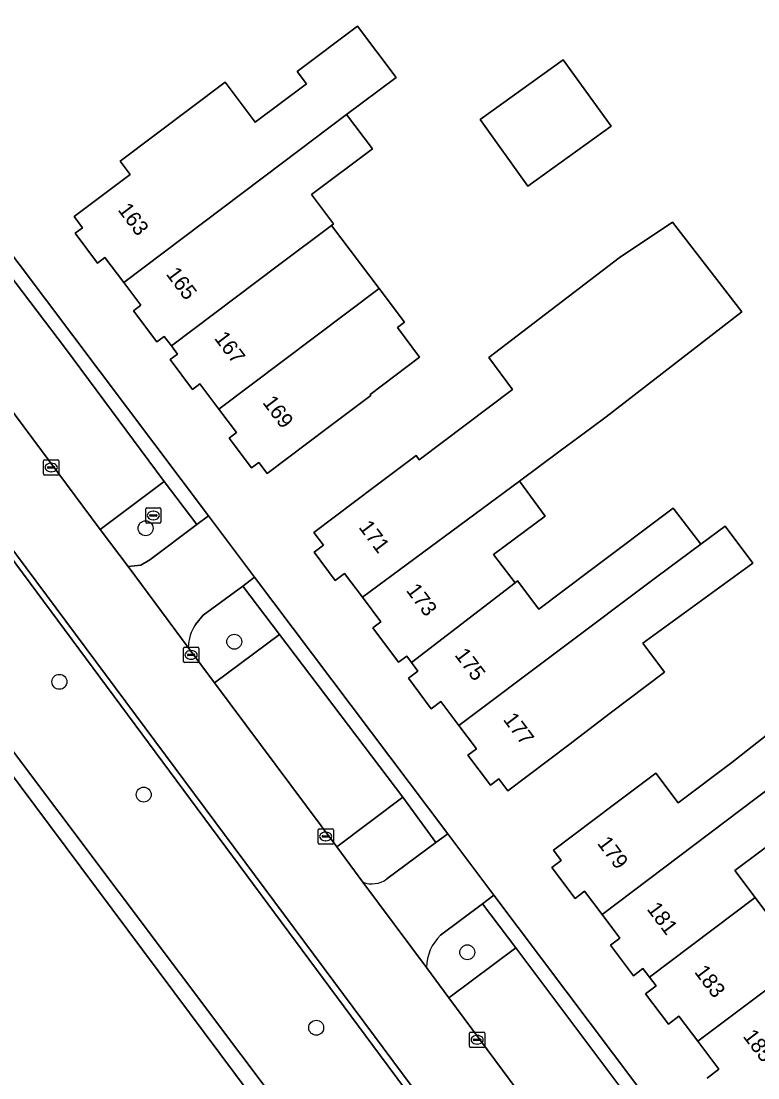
# Model space of a CAD drawing. Extents: x 164494 to 166241, y 382475 to 384495.
# Drawn here: x 165019 to 165067.3, y 383171.9 to 383241.1 of the extents above; entities that cross this region are included whole.
import ezdxf

# ---------------------------------------------------------------- set-up
doc = ezdxf.new("R2010")
doc.units = 0
for name, color, linetype in [('IMGEO_Berm_halfverhard', 7, 'Continuous'), ('IMGEO_Boom', 7, 'Continuous'), ('IMGEO_Erf', 7, 'Continuous'), ('IMGEO_Grasland_agrarisch', 7, 'Continuous'), ('IMGEO_Groenvoorziening', 7, 'Continuous'), ('IMGEO_Haag', 7, 'Continuous'), ('IMGEO_Hek', 7, 'Continuous'), ('IMGEO_Kolk', 7, 'Continuous'), ('IMGEO_Pand', 7, 'Continuous'), ('IMGEO_Pand_nummerreeks', 7, 'Continuous'), ('IMGEO_Parkeervlak_open', 7, 'Continuous'), ('IMGEO_Rijbaan_lokaal_gesloten', 7, 'Continuous'), ('IMGEO_Rioolput', 7, 'Continuous'), ('IMGEO_Voetpad_open', 7, 'Continuous')]:
    doc.layers.add(name, color=color, linetype=linetype)

msp = doc.modelspace()

# ---------------------------------------------------------------- linework, layer by layer
at = {"layer": 'IMGEO_Berm_halfverhard'}
msp.add_lwpolyline([(164958.624, 383286.837), (164958.165, 383286.487), (164958.551, 383285.995), (164958.685, 383286.071), (164960.201, 383284.12), (164981.497, 383255.445), (165004.699, 383224.274), (165010.162, 383216.934), (165012.663, 383213.574), (165041.519, 383174.67), (165059.934, 383149.875), (165074.189, 383130.821), (165074.54, 383131.069), (165010.834, 383216.638), (165007.308, 383221.332), (165004.939, 383224.601), (164967.779, 383274.687)], close=True, dxfattribs=at)
at = {"layer": 'IMGEO_Boom'}
for centre in [(165027.124, 383207.892), (165032.942, 383200.456), (165021.479, 383197.829), (165027.003, 383190.44), (165048.216, 383180.108), (165038.31, 383175.163)]:
    msp.add_circle(centre, 0.489, dxfattribs=at)
at = {"layer": 'IMGEO_Erf'}
for points in [[(165015.239, 383229.95), (165031.244, 383208.7), (165034.273, 383204.678), (165046.93, 383187.872), (165049.957, 383183.853), (165062.528, 383167.161), (165066.135, 383162.372), (165069.455, 383163.492), (165113.129, 383179.617), (165117.672, 383182.875), (165120.913, 383186.942), (165121.542, 383188.741), (165121.938, 383191.314), (165121.806, 383193.491), (165121.345, 383196.328), (165115.938, 383208.997), (165099.323, 383243.435)], [(165063.937, 383171.865), (165064.71, 383172.45), (165063.327, 383174.281), (165062.085, 383175.926), (165061.398, 383175.407), (165059.901, 383177.389), (165060.588, 383177.908), (165060.161, 383178.473), (165059.728, 383179.046), (165059.102, 383178.573), (165057.593, 383180.571), (165058.22, 383181.044), (165057.061, 383182.578), (165055.907, 383184.106), (165055.28, 383183.633), (165053.752, 383185.657), (165054.378, 383186.13), (165053.869, 383186.804), (165057.867, 383189.808), (165060.586, 383191.852), (165062.046, 383189.909), (165065.549, 383192.541), (165073.025, 383198.419)], [(165069.021, 383187.921), (165065.758, 383185.469), (165067.089, 383183.698), (165068.56, 383181.741)]]:
    msp.add_lwpolyline(points, dxfattribs=at)
for points in [[(165040.306, 383234.996), (165041.999, 383232.745), (165037.992, 383229.754), (165039.442, 383227.824), (165039.32, 383227.733), (165042.434, 383223.59), (165044.092, 383221.384), (165043.63, 383221.036), (165045.093, 383219.09), (165041.852, 383216.653), (165041.899, 383216.591), (165039.091, 383214.48), (165035.095, 383211.477), (165034.545, 383212.208), (165034.065, 383211.847), (165032.597, 383213.802), (165033.077, 383214.162), (165031.936, 383215.681), (165030.685, 383217.345), (165030.205, 383216.984), (165028.74, 383218.935), (165029.22, 383219.295), (165028.815, 383219.834), (165028.345, 383220.458), (165027.866, 383220.098), (165026.332, 383222.139), (165026.812, 383222.499), (165025.693, 383223.987), (165024.46, 383225.628), (165023.981, 383225.268), (165022.515, 383227.218), (165022.994, 383227.578), (165022.444, 383228.31), (165026.116, 383231.071), (165025.463, 383231.939), (165032.34, 383237.107), (165034.309, 383234.487), (165037.665, 383237.013), (165037.064, 383237.812), (165041.018, 383240.789), (165043.542, 383237.432)], [(165052.184, 383230.308), (165049.053, 383234.664), (165054.509, 383238.585), (165057.64, 383234.23)], [(165058.178, 383225.614), (165061.671, 383227.945), (165066.223, 383222.066), (165057.315, 383215.185), (165056.376, 383214.489), (165054.302, 383212.954), (165051.631, 383210.976), (165053.321, 383208.692), (165049.929, 383206.18), (165051.355, 383204.324), (165051.511, 383204.444), (165052.899, 383202.597), (165056.183, 383205.065), (165061.704, 383209.216), (165063.52, 383206.844), (165065.122, 383208.035), (165066.933, 383205.599), (165059.726, 383200.352), (165061.149, 383198.459), (165057.586, 383195.781), (165054.871, 383193.698), (165050.874, 383190.694), (165050.291, 383191.47), (165049.732, 383191.049), (165048.25, 383193.021), (165048.81, 383193.441), (165047.656, 383194.976), (165046.486, 383196.532), (165045.857, 383196.059), (165044.352, 383198.061), (165044.982, 383198.534), (165044.554, 383199.103), (165044.243, 383199.517), (165043.706, 383199.114), (165042.014, 383201.366), (165042.551, 383201.769), (165041.352, 383203.364), (165040.174, 383204.932), (165039.56, 383204.471), (165038.171, 383206.319), (165038.784, 383206.78), (165038.158, 383207.613), (165042.156, 383210.617), (165044.86, 383212.649), (165045.063, 383212.378), (165051.186, 383216.981), (165049.617, 383219.07)]]:
    msp.add_lwpolyline(points, close=True, dxfattribs=at)
at = {"layer": 'IMGEO_Grasland_agrarisch'}
msp.add_lwpolyline([(164980.914, 383148.382), (164984.464, 383145.593), (164986.079, 383147.55), (164989.095, 383145.351), (164987.398, 383143.288), (164988.7, 383142.265), (164990.041, 383144.274), (164992.369, 383142.607), (164990.882, 383140.55), (164991.336, 383140.194), (164999.033, 383132.273), (165005.383, 383122.26), (165055.217, 383142.364), (165001.686, 383214.058), (164971.559, 383197.218), (164924.278, 383170.366), (164950.628, 383163.159), (164961.434, 383158.935), (164968.553, 383155.492), (164979.763, 383149.202), (164979.818, 383149.302), (164980.837, 383150.538), (164981.966, 383149.612), (164980.98, 383148.501)], close=True, dxfattribs=at)
at = {"layer": 'IMGEO_Groenvoorziening'}
for points in [[(165131.174, 383055.545), (165127.167, 383060.515), (165121.14, 383068.038), (165114.948, 383075.929), (165110.383, 383081.771), (165084.231, 383116.963), (165084.718, 383117.313), (165084.235, 383117.963), (165074.593, 383130.998), (165074.54, 383131.069), (165074.189, 383130.821), (165059.934, 383149.875), (165041.519, 383174.67), (165012.663, 383213.574), (165010.162, 383216.934)], [(165004.905, 383120.773), (165057.111, 383141.834), (165001.652, 383215.597), (164998.338, 383213.696), (164970.712, 383197.845), (164920.991, 383170.02), (164950.25, 383162.018), (164960.954, 383157.835), (164967.997, 383154.428), (164979.176, 383148.155), (164979.763, 383149.202), (164968.553, 383155.492), (164961.434, 383158.935), (164950.628, 383163.159), (164924.278, 383170.366), (164971.559, 383197.218), (165001.686, 383214.058), (165055.217, 383142.364), (165005.383, 383122.26)], [(165001.652, 383215.597), (165057.111, 383141.834), (165064.424, 383130.625), (165069.489, 383132.355)], [(165029.916, 383200.087), (165031.646, 383197.767), (165035.91, 383200.939), (165033.499, 383204.106), (165030.905, 383202.188), (165030.4, 383201.58)], [(165042.937, 383184.911), (165046.148, 383187.292), (165043.994, 383190.272), (165039.657, 383187.007), (165041.362, 383184.698)], [(165045.531, 383179.12), (165047.015, 383177.125), (165051.395, 383180.401), (165049.207, 383183.29), (165046.456, 383181.223)]]:
    msp.add_lwpolyline(points, dxfattribs=at)
msp.add_lwpolyline([(165026.806, 383205.467), (165027.415, 383205.813), (165030.492, 383208.133), (165028.355, 383210.944), (165024.153, 383207.813), (165025.987, 383205.384)], close=True, dxfattribs=at)
for centre, radius, start, end in [((165032.787, 383199.981), 2.873, 146.18542, 177.89132), ((165041.952, 383186.268), 1.677, 249.41318, 305.99051), ((165048.637, 383179.009), 3.108, 134.56655, 177.94907)]:
    msp.add_arc(centre, radius, start, end, dxfattribs=at)
at = {"layer": 'IMGEO_Haag'}
msp.add_lwpolyline([(165004.905, 383120.773), (165057.111, 383141.834), (165001.652, 383215.597), (164998.338, 383213.696), (164970.712, 383197.845), (164920.991, 383170.02), (164950.25, 383162.018), (164960.954, 383157.835), (164967.997, 383154.428), (164979.176, 383148.155), (164979.763, 383149.202), (164968.553, 383155.492), (164961.434, 383158.935), (164950.628, 383163.159), (164924.278, 383170.366), (164971.559, 383197.218), (165001.686, 383214.058), (165055.217, 383142.364), (165005.383, 383122.26)], dxfattribs=at)
at = {"layer": 'IMGEO_Hek'}
msp.add_lwpolyline([(165005.383, 383122.26), (165055.217, 383142.364), (165001.686, 383214.058), (164971.559, 383197.218), (164924.278, 383170.366), (164950.628, 383163.159), (164961.434, 383158.935), (164968.553, 383155.492), (164979.763, 383149.202)], dxfattribs=at)
at = {"layer": 'IMGEO_Kolk'}
for p, q in [((165020.44, 383211.447), (165020.44, 383212.299)), ((165020.515, 383212.373), (165021.367, 383212.373)), ((165020.699, 383211.867), (165020.699, 383211.879)), ((165021.137, 383211.83), (165020.739, 383211.83)), ((165020.742, 383211.916), (165021.14, 383211.916)), ((165020.928, 383212.153), (165020.953, 383212.153)), ((165021.183, 383211.879), (165021.183, 383211.867)), ((165021.441, 383212.299), (165021.441, 383211.447)), ((165021.367, 383211.373), (165020.515, 383211.373)), ((165020.951, 383211.593), (165020.926, 383211.593)), ((165029.61, 383199.166), (165029.61, 383200.018)), ((165029.685, 383200.092), (165030.537, 383200.092)), ((165030.611, 383200.018), (165030.611, 383199.166)), ((165029.869, 383199.586), (165029.869, 383199.598)), ((165030.307, 383199.549), (165029.909, 383199.549)), ((165029.912, 383199.635), (165030.31, 383199.635)), ((165030.121, 383199.312), (165030.096, 383199.312)), ((165030.098, 383199.872), (165030.123, 383199.872)), ((165030.353, 383199.598), (165030.353, 383199.586)), ((165030.537, 383199.092), (165029.685, 383199.092)), ((165038.433, 383187.271), (165038.433, 383188.123)), ((165038.508, 383188.197), (165039.36, 383188.197)), ((165038.692, 383187.691), (165038.692, 383187.703)), ((165039.13, 383187.654), (165038.732, 383187.654)), ((165038.735, 383187.74), (165039.133, 383187.74)), ((165038.921, 383187.977), (165038.946, 383187.977)), ((165039.176, 383187.703), (165039.176, 383187.691)), ((165039.434, 383188.123), (165039.434, 383187.271)), ((165039.36, 383187.197), (165038.508, 383187.197)), ((165038.944, 383187.417), (165038.919, 383187.417)), ((165048.36, 383173.953), (165048.36, 383174.805)), ((165048.435, 383174.879), (165049.287, 383174.879)), ((165048.619, 383174.373), (165048.619, 383174.385)), ((165048.662, 383174.422), (165049.06, 383174.422)), ((165048.848, 383174.659), (165048.873, 383174.659)), ((165049.103, 383174.385), (165049.103, 383174.373)), ((165049.361, 383174.805), (165049.361, 383173.953)), ((165049.287, 383173.879), (165048.435, 383173.879)), ((165049.057, 383174.336), (165048.659, 383174.336)), ((165048.871, 383174.099), (165048.846, 383174.099))]:
    msp.add_line(p, q, dxfattribs=at)
for points in [[(165020.44, 383211.447), (165020.44, 383212.299)], [(165020.515, 383212.373), (165021.367, 383212.373)], [(165021.441, 383212.299), (165021.441, 383211.447)], [(165021.367, 383211.373), (165020.515, 383211.373)], [(165029.61, 383199.166), (165029.61, 383200.018)], [(165029.685, 383200.092), (165030.537, 383200.092)], [(165030.611, 383200.018), (165030.611, 383199.166)], [(165030.537, 383199.092), (165029.685, 383199.092)], [(165038.433, 383187.271), (165038.433, 383188.123)], [(165038.508, 383188.197), (165039.36, 383188.197)], [(165039.434, 383188.123), (165039.434, 383187.271)], [(165039.36, 383187.197), (165038.508, 383187.197)], [(165048.36, 383173.953), (165048.36, 383174.805)], [(165048.435, 383174.879), (165049.287, 383174.879)], [(165049.361, 383174.805), (165049.361, 383173.953)], [(165049.287, 383173.879), (165048.435, 383173.879)]]:
    msp.add_lwpolyline(points, dxfattribs=at)
for centre, radius, start, end in [((165020.517, 383212.297), 0.0765, 91.55205, 178.44795), ((165020.517, 383212.297), 0.0765, 91.55205, 178.44795), ((165020.739, 383211.876), 0.0403, 85.87752, 175.75265), ((165020.736, 383211.866), 0.0366, 178.93798, 274.71019), ((165021.14, 383211.873), 0.043, 264.86636, 352.45326), ((165021.144, 383211.878), 0.0386, 1.73085, 96.63898), ((165021.365, 383212.297), 0.0765, 1.55205, 88.44795), ((165021.365, 383212.297), 0.0765, 1.55205, 88.44795), ((165020.517, 383211.449), 0.0765, 181.55205, 268.44795), ((165020.517, 383211.449), 0.0765, 181.55205, 268.44795), ((165021.365, 383211.449), 0.0765, 271.55205, 358.44795), ((165021.365, 383211.449), 0.0765, 271.55205, 358.44795), ((165029.687, 383200.016), 0.0765, 91.55205, 178.44795), ((165029.687, 383200.016), 0.0765, 91.55205, 178.44795), ((165030.535, 383200.016), 0.0765, 1.55205, 88.44795), ((165030.535, 383200.016), 0.0765, 1.55205, 88.44795), ((165029.909, 383199.595), 0.0403, 85.87752, 175.75265), ((165029.906, 383199.585), 0.0366, 178.93798, 274.71019), ((165030.31, 383199.592), 0.043, 264.86636, 352.45326), ((165030.314, 383199.597), 0.0386, 1.73085, 96.63898), ((165029.687, 383199.168), 0.0765, 181.55205, 268.44795), ((165029.687, 383199.168), 0.0765, 181.55205, 268.44795), ((165030.535, 383199.168), 0.0765, 271.55205, 358.44795), ((165030.535, 383199.168), 0.0765, 271.55205, 358.44795), ((165038.51, 383188.121), 0.0765, 91.55205, 178.44795), ((165038.51, 383188.121), 0.0765, 91.55205, 178.44795), ((165038.732, 383187.7), 0.0403, 85.87752, 175.75265), ((165038.729, 383187.69), 0.0366, 178.93798, 274.71019), ((165039.133, 383187.697), 0.043, 264.86636, 352.45326), ((165039.137, 383187.702), 0.0386, 1.73085, 96.63898), ((165039.358, 383188.121), 0.0765, 1.55205, 88.44795), ((165039.358, 383188.121), 0.0765, 1.55205, 88.44795), ((165038.51, 383187.273), 0.0765, 181.55205, 268.44795), ((165038.51, 383187.273), 0.0765, 181.55205, 268.44795), ((165039.358, 383187.273), 0.0765, 271.55205, 358.44795), ((165039.358, 383187.273), 0.0765, 271.55205, 358.44795), ((165048.437, 383174.803), 0.0765, 91.55205, 178.44795), ((165048.437, 383174.803), 0.0765, 91.55205, 178.44795), ((165048.659, 383174.382), 0.0403, 85.87752, 175.75265), ((165048.656, 383174.372), 0.0366, 178.93798, 274.71019), ((165049.06, 383174.379), 0.043, 264.86636, 352.45326), ((165049.064, 383174.384), 0.0386, 1.73085, 96.63898), ((165049.285, 383174.803), 0.0765, 1.55205, 88.44795), ((165049.285, 383174.803), 0.0765, 1.55205, 88.44795), ((165048.437, 383173.955), 0.0765, 181.55205, 268.44795), ((165048.437, 383173.955), 0.0765, 181.55205, 268.44795), ((165049.285, 383173.955), 0.0765, 271.55205, 358.44795), ((165049.285, 383173.955), 0.0765, 271.55205, 358.44795)]:
    msp.add_arc(centre, radius, start, end, dxfattribs=at)
for centre, major_axis, ratio, start_param, end_param in [((165020.927, 383211.873), (-0.387, 0.002), 0.722429, 4.712389, 7.853982), ((165020.952, 383211.873), (-0.39, 0.002), 0.717154, 1.570796, 4.712389), ((165030.097, 383199.592), (-0.387, 0.002), 0.722429, 4.712389, 7.853982), ((165030.122, 383199.592), (-0.39, 0.002), 0.717154, 1.570796, 4.712389), ((165038.92, 383187.697), (-0.387, 0.002), 0.722429, 4.712389, 7.853982), ((165038.945, 383187.697), (-0.39, 0.002), 0.717154, 1.570796, 4.712389), ((165048.847, 383174.379), (-0.387, 0.002), 0.722429, 4.712389, 7.853982), ((165048.872, 383174.379), (-0.39, 0.002), 0.717154, 1.570796, 4.712389)]:
    msp.add_ellipse(centre, major_axis=major_axis, ratio=ratio, start_param=start_param, end_param=end_param, dxfattribs=at)
at = {"layer": 'IMGEO_Pand'}
for points in [[(165040.306, 383234.996), (165043.542, 383237.432), (165041.018, 383240.789), (165037.064, 383237.812), (165037.665, 383237.013), (165034.309, 383234.487), (165032.34, 383237.107), (165025.463, 383231.939), (165026.116, 383231.071), (165022.444, 383228.31), (165022.994, 383227.578), (165022.515, 383227.218), (165023.981, 383225.268), (165024.46, 383225.628), (165025.693, 383223.987), (165036.095, 383231.826)], [(165054.509, 383238.585), (165049.053, 383234.664), (165052.184, 383230.308), (165057.64, 383234.23)], [(165039.32, 383227.733), (165039.442, 383227.824), (165037.992, 383229.754), (165041.999, 383232.745), (165040.306, 383234.996), (165036.095, 383231.826), (165025.693, 383223.987), (165026.812, 383222.499), (165026.332, 383222.139), (165027.866, 383220.098), (165028.345, 383220.458), (165028.815, 383219.834), (165035.845, 383225.12)], [(165042.434, 383223.59), (165039.32, 383227.733), (165035.845, 383225.12), (165028.815, 383219.834), (165029.22, 383219.295), (165028.74, 383218.935), (165030.205, 383216.984), (165030.685, 383217.345), (165031.936, 383215.681)], [(165051.631, 383210.976), (165054.302, 383212.954), (165056.376, 383214.489), (165057.315, 383215.185), (165066.223, 383222.066), (165061.671, 383227.945), (165058.178, 383225.614), (165049.617, 383219.07), (165051.186, 383216.981), (165045.063, 383212.378), (165044.86, 383212.649), (165042.156, 383210.617), (165038.158, 383207.613), (165038.784, 383206.78), (165038.171, 383206.319), (165039.56, 383204.471), (165040.174, 383204.932), (165041.352, 383203.364)], [(165042.434, 383223.59), (165031.936, 383215.681), (165033.077, 383214.162), (165032.597, 383213.802), (165034.065, 383211.847), (165034.545, 383212.208), (165035.095, 383211.477), (165039.091, 383214.48), (165041.899, 383216.591), (165041.852, 383216.653), (165045.093, 383219.09), (165043.63, 383221.036), (165044.092, 383221.384)], [(165069.932, 383192.285), (165072.484, 383194.21), (165075.031, 383196.131), (165087.792, 383205.569), (165083.664, 383211.659), (165076.095, 383206.151), (165078.583, 383202.656), (165073.025, 383198.419), (165065.549, 383192.541), (165062.046, 383189.909), (165060.586, 383191.852), (165057.867, 383189.808), (165053.869, 383186.804), (165054.378, 383186.13), (165053.752, 383185.657), (165055.28, 383183.633), (165055.907, 383184.106), (165057.061, 383182.578), (165067.16, 383190.195)], [(165051.631, 383210.976), (165041.352, 383203.364), (165042.551, 383201.769), (165042.014, 383201.366), (165043.706, 383199.114), (165044.243, 383199.517), (165044.554, 383199.103), (165051.355, 383204.324), (165049.929, 383206.18), (165053.321, 383208.692)], [(165060.641, 383204.704), (165063.52, 383206.844), (165061.704, 383209.216), (165056.183, 383205.065), (165052.899, 383202.597), (165051.511, 383204.444), (165051.355, 383204.324), (165044.554, 383199.103), (165044.982, 383198.534), (165044.352, 383198.061), (165045.857, 383196.059), (165046.486, 383196.532), (165047.656, 383194.976)], [(165061.149, 383198.459), (165059.726, 383200.352), (165066.933, 383205.599), (165065.122, 383208.035), (165063.52, 383206.844), (165060.641, 383204.704), (165047.656, 383194.976), (165048.81, 383193.441), (165048.25, 383193.021), (165049.732, 383191.049), (165050.291, 383191.47), (165050.874, 383190.694), (165054.871, 383193.698), (165057.586, 383195.781)], [(165071.696, 383189.901), (165069.932, 383192.285), (165067.16, 383190.195), (165057.061, 383182.578), (165058.22, 383181.044), (165057.593, 383180.571), (165059.102, 383178.573), (165059.728, 383179.046), (165060.161, 383178.473), (165067.089, 383183.698), (165065.758, 383185.469), (165069.021, 383187.921)], [(165078.372, 383185.544), (165076.657, 383187.826), (165071.802, 383184.178), (165068.56, 383181.741), (165067.089, 383183.698), (165060.161, 383178.473), (165060.588, 383177.908), (165059.901, 383177.389), (165061.398, 383175.407), (165062.085, 383175.926), (165063.327, 383174.281)]]:
    msp.add_lwpolyline(points, close=True, dxfattribs=at)
msp.add_lwpolyline([(165076.723, 383171.76), (165076.536, 383172.007), (165076.129, 383171.7), (165073.526, 383175.147), (165077.499, 383178.149), (165077.807, 383177.742), (165078.054, 383177.929), (165077.747, 383178.336), (165081.545, 383181.204), (165081.853, 383180.797), (165082.1, 383180.984), (165084.045, 383178.409), (165097.149, 383188.306), (165092.15, 383194.924), (165079.047, 383185.026), (165078.553, 383185.68), (165078.372, 383185.544), (165063.327, 383174.281), (165064.71, 383172.45), (165063.937, 383171.865)], dxfattribs=at)
at = {"layer": 'IMGEO_Parkeervlak_open'}
for points in [[(165010.316, 383226.399), (165024.153, 383207.813), (165028.355, 383210.944), (165021.887, 383219.675), (165014.428, 383229.447)], [(165039.657, 383187.007), (165043.994, 383190.272), (165035.91, 383200.939), (165031.646, 383197.767)], [(165051.395, 383180.401), (165047.015, 383177.125), (165054.99, 383166.374), (165059.454, 383169.659)]]:
    msp.add_lwpolyline(points, close=True, dxfattribs=at)
at = {"layer": 'IMGEO_Rijbaan_lokaal_gesloten'}
for points in [[(165074.593, 383130.998), (165078.641, 383134.022), (165066.076, 383150.934), (165060.749, 383158.104), (165061.002, 383158.295), (165057.36, 383163.251), (165054.99, 383166.374), (165047.015, 383177.125), (165045.531, 383179.12), (165041.362, 383184.698), (165039.657, 383187.007), (165031.646, 383197.767), (165029.916, 383200.087), (165025.987, 383205.384), (165024.153, 383207.813), (165010.316, 383226.399)], [(165010.834, 383216.638), (165074.54, 383131.069)]]:
    msp.add_lwpolyline(points, dxfattribs=at)
at = {"layer": 'IMGEO_Rioolput'}
for p, q in [((165027.134, 383208.301), (165027.134, 383209.153)), ((165027.209, 383209.227), (165028.061, 383209.227)), ((165027.622, 383209.007), (165027.647, 383209.007)), ((165028.135, 383209.153), (165028.135, 383208.301)), ((165027.393, 383208.721), (165027.393, 383208.733)), ((165027.831, 383208.684), (165027.433, 383208.684)), ((165027.436, 383208.77), (165027.834, 383208.77)), ((165027.645, 383208.447), (165027.62, 383208.447)), ((165027.877, 383208.733), (165027.877, 383208.721)), ((165028.061, 383208.227), (165027.209, 383208.227))]:
    msp.add_line(p, q, dxfattribs=at)
for points in [[(165027.134, 383208.301), (165027.134, 383209.153)], [(165027.209, 383209.227), (165028.061, 383209.227)], [(165028.135, 383209.153), (165028.135, 383208.301)], [(165028.061, 383208.227), (165027.209, 383208.227)]]:
    msp.add_lwpolyline(points, dxfattribs=at)
for centre, radius, start, end in [((165027.211, 383209.151), 0.0765, 91.55205, 178.44795), ((165027.211, 383209.151), 0.0765, 91.55205, 178.44795), ((165028.059, 383209.151), 0.0765, 1.55205, 88.44795), ((165028.059, 383209.151), 0.0765, 1.55205, 88.44795), ((165027.211, 383208.303), 0.0765, 181.55205, 268.44795), ((165027.211, 383208.303), 0.0765, 181.55205, 268.44795), ((165027.433, 383208.73), 0.0403, 85.87752, 175.75265), ((165027.43, 383208.72), 0.0366, 178.93798, 274.71019), ((165027.834, 383208.727), 0.043, 264.86636, 352.45326), ((165027.838, 383208.732), 0.0386, 1.73085, 96.63898), ((165028.059, 383208.303), 0.0765, 271.55205, 358.44795), ((165028.059, 383208.303), 0.0765, 271.55205, 358.44795)]:
    msp.add_arc(centre, radius, start, end, dxfattribs=at)
for centre, major_axis, ratio, start_param, end_param in [((165027.621, 383208.727), (-0.387, 0.002), 0.722429, 4.712389, 7.853982), ((165027.646, 383208.727), (-0.39, 0.002), 0.717154, 1.570796, 4.712389)]:
    msp.add_ellipse(centre, major_axis=major_axis, ratio=ratio, start_param=start_param, end_param=end_param, dxfattribs=at)
at = {"layer": 'IMGEO_Voetpad_open'}
for points in [[(165012.159, 383232.511), (165014.428, 383229.447), (165021.887, 383219.675), (165028.355, 383210.944), (165030.492, 383208.133), (165031.244, 383208.7), (165015.239, 383229.95), (165012.902, 383233.067)], [(165035.91, 383200.939), (165043.994, 383190.272), (165046.148, 383187.292), (165046.93, 383187.872), (165034.273, 383204.678), (165033.499, 383204.106)], [(165062.528, 383167.161), (165049.957, 383183.853), (165049.207, 383183.29), (165051.395, 383180.401), (165059.454, 383169.659), (165061.726, 383166.554)]]:
    msp.add_lwpolyline(points, close=True, dxfattribs=at)
for points in [[(165030.4, 383201.58), (165030.905, 383202.188), (165033.499, 383204.106), (165034.273, 383204.678), (165031.244, 383208.7), (165030.492, 383208.133), (165027.415, 383205.813), (165026.806, 383205.467), (165025.987, 383205.384), (165029.916, 383200.087)], [(165046.456, 383181.223), (165049.207, 383183.29), (165049.957, 383183.853), (165046.93, 383187.872), (165046.148, 383187.292), (165042.937, 383184.911)], [(165041.362, 383184.698), (165045.531, 383179.12)]]:
    msp.add_lwpolyline(points, dxfattribs=at)
for centre, radius, start, end in [((165032.787, 383199.981), 2.873, 146.18542, 177.89132), ((165041.952, 383186.268), 1.677, 249.41318, 305.99051), ((165048.637, 383179.009), 3.108, 134.56655, 177.94907)]:
    msp.add_arc(centre, radius, start, end, dxfattribs=at)

# ---------------------------------------------------------------- texts
at = {"layer": 'IMGEO_Pand_nummerreeks'}
for s, rotation, p in [('163', 306.92692, (165025.266, 383228.748)), ('165', 306.92692, (165028.428, 383224.54)), ('167', 306.92692, (165031.591, 383220.332)), ('169', 306.92692, (165034.754, 383216.123)), ('171', 306.92692, (165041.057, 383207.949)), ('173', 306.92692, (165044.167, 383203.811)), ('175', 306.92692, (165047.346, 383199.581)), ('177', 306.92692, (165050.525, 383195.351)), ('179', 307.06443, (165056.695, 383187.243)), ('181', 307.06443, (165059.947, 383182.937)), ('183', 307.06443, (165063.062, 383178.813)), ('185', 307.06443, (165066.245, 383174.598))]:
    msp.add_text(s, height=1, rotation=rotation, dxfattribs=at).set_placement(p)

doc.saveas('drawing.dxf')
